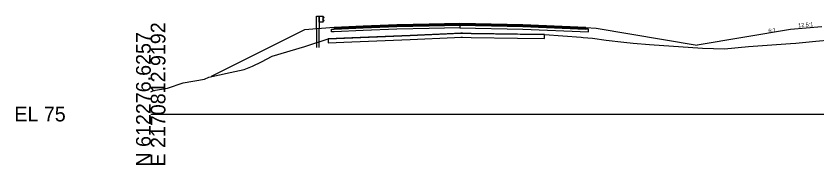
# Model space of a CAD drawing. Extents: x -26 to 1303, y -3010 to 12023.
# Drawn here: x -25.7 to 126.9, y 10490.3 to 10518.7 of the extents above; entities that cross this region are included whole.
import ezdxf

# ---------------------------------------------------------------- set-up
doc = ezdxf.new("R2010")
doc.units = 0
for name, color, linetype in [('RD_GPK_XS_Cell', 7, 'Continuous'), ('RD_PD_Final_TrvlWay', 7, 'Continuous'), ('RD_XS_Base', 7, 'Continuous'), ('RD_XS_ExGround', 7, 'Continuous'), ('RD_XS_ExPaveRet', 7, 'Continuous'), ('RD_XS_GR', 7, 'Continuous'), ('RD_XS_Greenside', 7, 'Continuous'), ('RD_XS_Pave', 7, 'Continuous'), ('RD_XS_PaveOvlay_CP', 7, 'Continuous'), ('RD_XS_TieSlope', 7, 'Continuous'), ('RD_XS_TX_ShdSlope', 7, 'Continuous'), ('RD_XS_TX_Slope', 7, 'Continuous')]:
    doc.layers.add(name, color=color, linetype=linetype)

msp = doc.modelspace()

# ---------------------------------------------------------------- linework, layer by layer
at = {"layer": 'RD_GPK_XS_Cell'}
msp.add_line((0, 10500), (150, 10500), dxfattribs=at)
at = {"layer": 'RD_PD_Final_TrvlWay'}
msp.add_lwpolyline([(32.13, 10512.68), (32.13, 10516.28), (31.63, 10516.24), (31.63, 10512.68)], dxfattribs=at)
at = {"layer": 'RD_XS_Base'}
for p, q in [((58.96, 10517), (58.96, 10517.07)), ((58.96, 10517.07), (58.96, 10516.76)), ((58.96, 10516.91), (58.96, 10517.07)), ((58.96, 10517.07), (58.96, 10516.41)), ((34.46, 10516.17), (34.68, 10516.18)), ((34.46, 10515.89), (34.46, 10516.17)), ((34.46, 10515.67), (34.46, 10515.89)), ((34.68, 10515.68), (34.46, 10515.67)), ((34.68, 10516.18), (34.96, 10516.19)), ((34.96, 10515.69), (34.68, 10515.68)), ((34.96, 10516.19), (40.51, 10516.41)), ((40.51, 10515.91), (34.96, 10515.69)), ((40.51, 10516.41), (46.96, 10516.67)), ((46.96, 10516.17), (40.51, 10515.91)), ((46.96, 10516.67), (53.12, 10516.79)), ((53.12, 10516.29), (46.96, 10516.17)), ((53.12, 10516.79), (58.96, 10516.91)), ((58.96, 10516.41), (53.12, 10516.29)), ((58.96, 10516.91), (58.96, 10517)), ((58.96, 10516.91), (58.96, 10516.68)), ((58.96, 10516.91), (58.96, 10516.41)), ((70.96, 10516.67), (58.96, 10516.91)), ((58.96, 10516.91), (58.96, 10516.91)), ((58.96, 10516.76), (58.96, 10516.41)), ((58.96, 10516.68), (58.96, 10516.41)), ((58.96, 10516.41), (58.96, 10516.41)), ((58.96, 10516.41), (58.96, 10516.41)), ((58.96, 10516.41), (70.96, 10516.17)), ((82.96, 10516.19), (70.96, 10516.67)), ((70.96, 10516.17), (83.46, 10515.67)), ((72.96, 10516.59), (72.96, 10516.59)), ((72.96, 10516.09), (72.96, 10516.09)), ((83.46, 10516.17), (82.96, 10516.19)), ((82.96, 10516.19), (82.96, 10516.19)), ((83.46, 10515.67), (83.46, 10516.17)), ((83.46, 10516.17), (83.46, 10516.17)), ((83.46, 10515.67), (83.46, 10515.67)), ((83.46, 10515.67), (83.46, 10515.67))]:
    msp.add_line(p, q, dxfattribs=at)
at = {"layer": 'RD_XS_ExGround'}
msp.add_lwpolyline([(0, 10504.22), (0.53, 10504.47), (3.21, 10504.91), (6.16, 10505.96), (10.24, 10506.67), (11.05, 10507.06), (15.14, 10507.95), (17.8, 10508.48), (19.41, 10509.13), (21.13, 10509.93), (23.18, 10511.04), (29.4, 10512.89), (33.81, 10514.33), (49.47, 10514.98), (59.16, 10515.39), (61.08, 10515.36), (75.08, 10515.17), (82.06, 10514.64), (82.48, 10514.61), (84.23, 10514.49), (86.82, 10514.07), (90.21, 10513.69), (92, 10513.5), (95.09, 10513.25), (105.19, 10512.54), (109.39, 10512.45), (113.99, 10512.87), (122, 10513.47), (123.02, 10513.5), (126.8, 10513.87), (132.55, 10514.4)], dxfattribs=at)
at = {"layer": 'RD_XS_ExPaveRet'}
msp.add_lwpolyline([(61.08, 10515.36), (59.42, 10515.39), (59.16, 10515.39), (57.95, 10515.34), (49.47, 10514.98), (38.35, 10514.52), (33.81, 10514.33), (33.81, 10514), (33.81, 10513.58), (38.35, 10513.77), (49.47, 10514.23), (57.95, 10514.59), (59.16, 10514.64), (59.42, 10514.64), (61.08, 10514.61), (69.93, 10514.49), (75.08, 10514.42), (75.08, 10514.72), (75.08, 10515.17), (69.93, 10515.24), (61.08, 10515.36)], dxfattribs=at)
msp.add_lwpolyline([(61.08, 10515.36), (59.42, 10515.39), (59.16, 10515.39), (57.95, 10515.34), (49.47, 10514.98), (38.35, 10514.52), (33.81, 10514.33), (33.81, 10514), (33.81, 10513.58), (38.35, 10513.77), (49.47, 10514.23), (57.95, 10514.59), (59.16, 10514.64), (59.42, 10514.64), (61.08, 10514.61), (69.93, 10514.49), (75.08, 10514.42), (75.08, 10514.72), (75.08, 10515.17), (69.93, 10515.24), (61.08, 10515.36)], dxfattribs=at)
at = {"layer": 'RD_XS_GR'}
for p, q in [((31.63, 10516.24), (31.63, 10518.68)), ((31.63, 10518.68), (31.88, 10518.68)), ((31.88, 10518.68), (32.13, 10518.68)), ((32.13, 10518.68), (32.13, 10516.28)), ((32.13, 10517.51), (32.13, 10518.68)), ((32.13, 10518.68), (32.79, 10518.68)), ((32.79, 10518.68), (32.79, 10517.51)), ((32.95, 10518.51), (32.79, 10518.68)), ((32.79, 10518.68), (32.79, 10518.01)), ((32.79, 10517.51), (32.13, 10517.51)), ((32.79, 10518.09), (32.91, 10518.22)), ((32.95, 10517.93), (32.79, 10518.09)), ((32.79, 10518.01), (32.79, 10517.51)), ((32.79, 10517.51), (32.91, 10517.64)), ((32.91, 10518.22), (33.07, 10518.39)), ((32.91, 10517.64), (33.07, 10517.8)), ((33.07, 10518.39), (32.95, 10518.51)), ((33.07, 10517.8), (32.95, 10517.93)), ((32.13, 10516.28), (31.63, 10516.24))]:
    msp.add_line(p, q, dxfattribs=at)
at = {"layer": 'RD_XS_Greenside'}
for p, q in [((29.32, 10516.06), (11.52, 10507.16)), ((84.96, 10516.35), (104.2, 10513.14)), ((122, 10516.11), (104.2, 10513.14))]:
    msp.add_line(p, q, dxfattribs=at)
at = {"layer": 'RD_XS_Pave'}
for p, q in [((53.12, 10517.11), (46.96, 10516.99)), ((58.96, 10517.23), (53.12, 10517.11)), ((58.96, 10517.07), (53.12, 10516.95)), ((53.12, 10516.95), (58.96, 10517.07)), ((70.96, 10516.99), (58.96, 10517.23)), ((58.96, 10517), (58.96, 10517.07)), ((58.96, 10517.07), (58.96, 10517)), ((58.96, 10516.91), (58.96, 10517.07)), ((58.96, 10517.07), (70.96, 10516.83)), ((70.96, 10516.83), (58.96, 10517.07)), ((58.96, 10517.07), (58.96, 10516.91)), ((40.51, 10516.73), (34.96, 10516.51)), ((40.51, 10516.57), (34.96, 10516.35)), ((34.96, 10516.35), (40.51, 10516.57)), ((34.96, 10516.51), (34.96, 10516.42)), ((34.96, 10516.42), (34.96, 10516.35)), ((34.96, 10516.19), (40.51, 10516.41)), ((34.96, 10516.35), (34.96, 10516.26)), ((34.96, 10516.26), (34.96, 10516.19)), ((46.96, 10516.99), (40.51, 10516.73)), ((46.96, 10516.83), (40.51, 10516.57)), ((40.51, 10516.57), (46.96, 10516.83)), ((40.51, 10516.41), (46.96, 10516.67)), ((53.12, 10516.95), (46.96, 10516.83)), ((46.96, 10516.83), (53.12, 10516.95)), ((46.96, 10516.67), (53.12, 10516.79)), ((53.12, 10516.79), (58.96, 10516.91)), ((58.96, 10516.91), (58.96, 10517)), ((58.96, 10517), (58.96, 10516.91)), ((58.96, 10516.91), (58.96, 10516.91)), ((58.96, 10516.91), (58.96, 10516.91)), ((58.96, 10516.91), (70.96, 10516.67)), ((82.96, 10516.51), (70.96, 10516.99)), ((70.96, 10516.83), (82.96, 10516.35)), ((82.96, 10516.35), (70.96, 10516.83)), ((70.96, 10516.67), (82.96, 10516.19)), ((72.96, 10516.91), (72.96, 10516.91)), ((72.96, 10516.75), (72.96, 10516.75)), ((72.96, 10516.75), (72.96, 10516.75)), ((72.96, 10516.59), (72.96, 10516.59)), ((82.96, 10516.35), (82.96, 10516.51)), ((82.96, 10516.51), (82.96, 10516.51)), ((82.96, 10516.35), (82.96, 10516.35)), ((82.96, 10516.35), (82.96, 10516.35)), ((82.96, 10516.19), (82.96, 10516.35)), ((82.96, 10516.35), (82.96, 10516.35)), ((82.96, 10516.19), (82.96, 10516.19)), ((82.96, 10516.19), (82.96, 10516.19))]:
    msp.add_line(p, q, dxfattribs=at)
at = {"layer": 'RD_XS_PaveOvlay_CP'}
for p, q in [((46.96, 10516.99), (58.96, 10517.23)), ((58.96, 10517.23), (70.96, 10516.99)), ((34.96, 10516.51), (46.96, 10516.99)), ((70.96, 10516.99), (82.96, 10516.51))]:
    msp.add_line(p, q, dxfattribs=at)
at = {"layer": 'RD_XS_TieSlope'}
for p, q in [((34.96, 10516.51), (29.32, 10516.06)), ((82.96, 10516.51), (84.96, 10516.35)), ((128, 10516.59), (122, 10516.11))]:
    msp.add_line(p, q, dxfattribs=at)

# ---------------------------------------------------------------- texts
at = {"layer": 'RD_GPK_XS_Cell'}
for s, p in [('E 2170812.9192', (2.8, 10490)), ('N 612276.6257', (0, 10490))]:
    msp.add_text(s, height=2.8, rotation=90, dxfattribs=at).set_placement(p)
msp.add_text('EL 75', height=2.8, dxfattribs=at).set_placement((-26, 10498.6))
at = {"layer": 'RD_XS_TX_ShdSlope'}
msp.add_text('12.5:1', height=0.75, rotation=4.5739, dxfattribs=at).set_placement((123.49, 10516.52))
at = {"layer": 'RD_XS_TX_Slope'}
msp.add_text('6:1', height=0.75, rotation=9.4623, dxfattribs=at).set_placement((117.85, 10515.47))

doc.saveas('drawing.dxf')
